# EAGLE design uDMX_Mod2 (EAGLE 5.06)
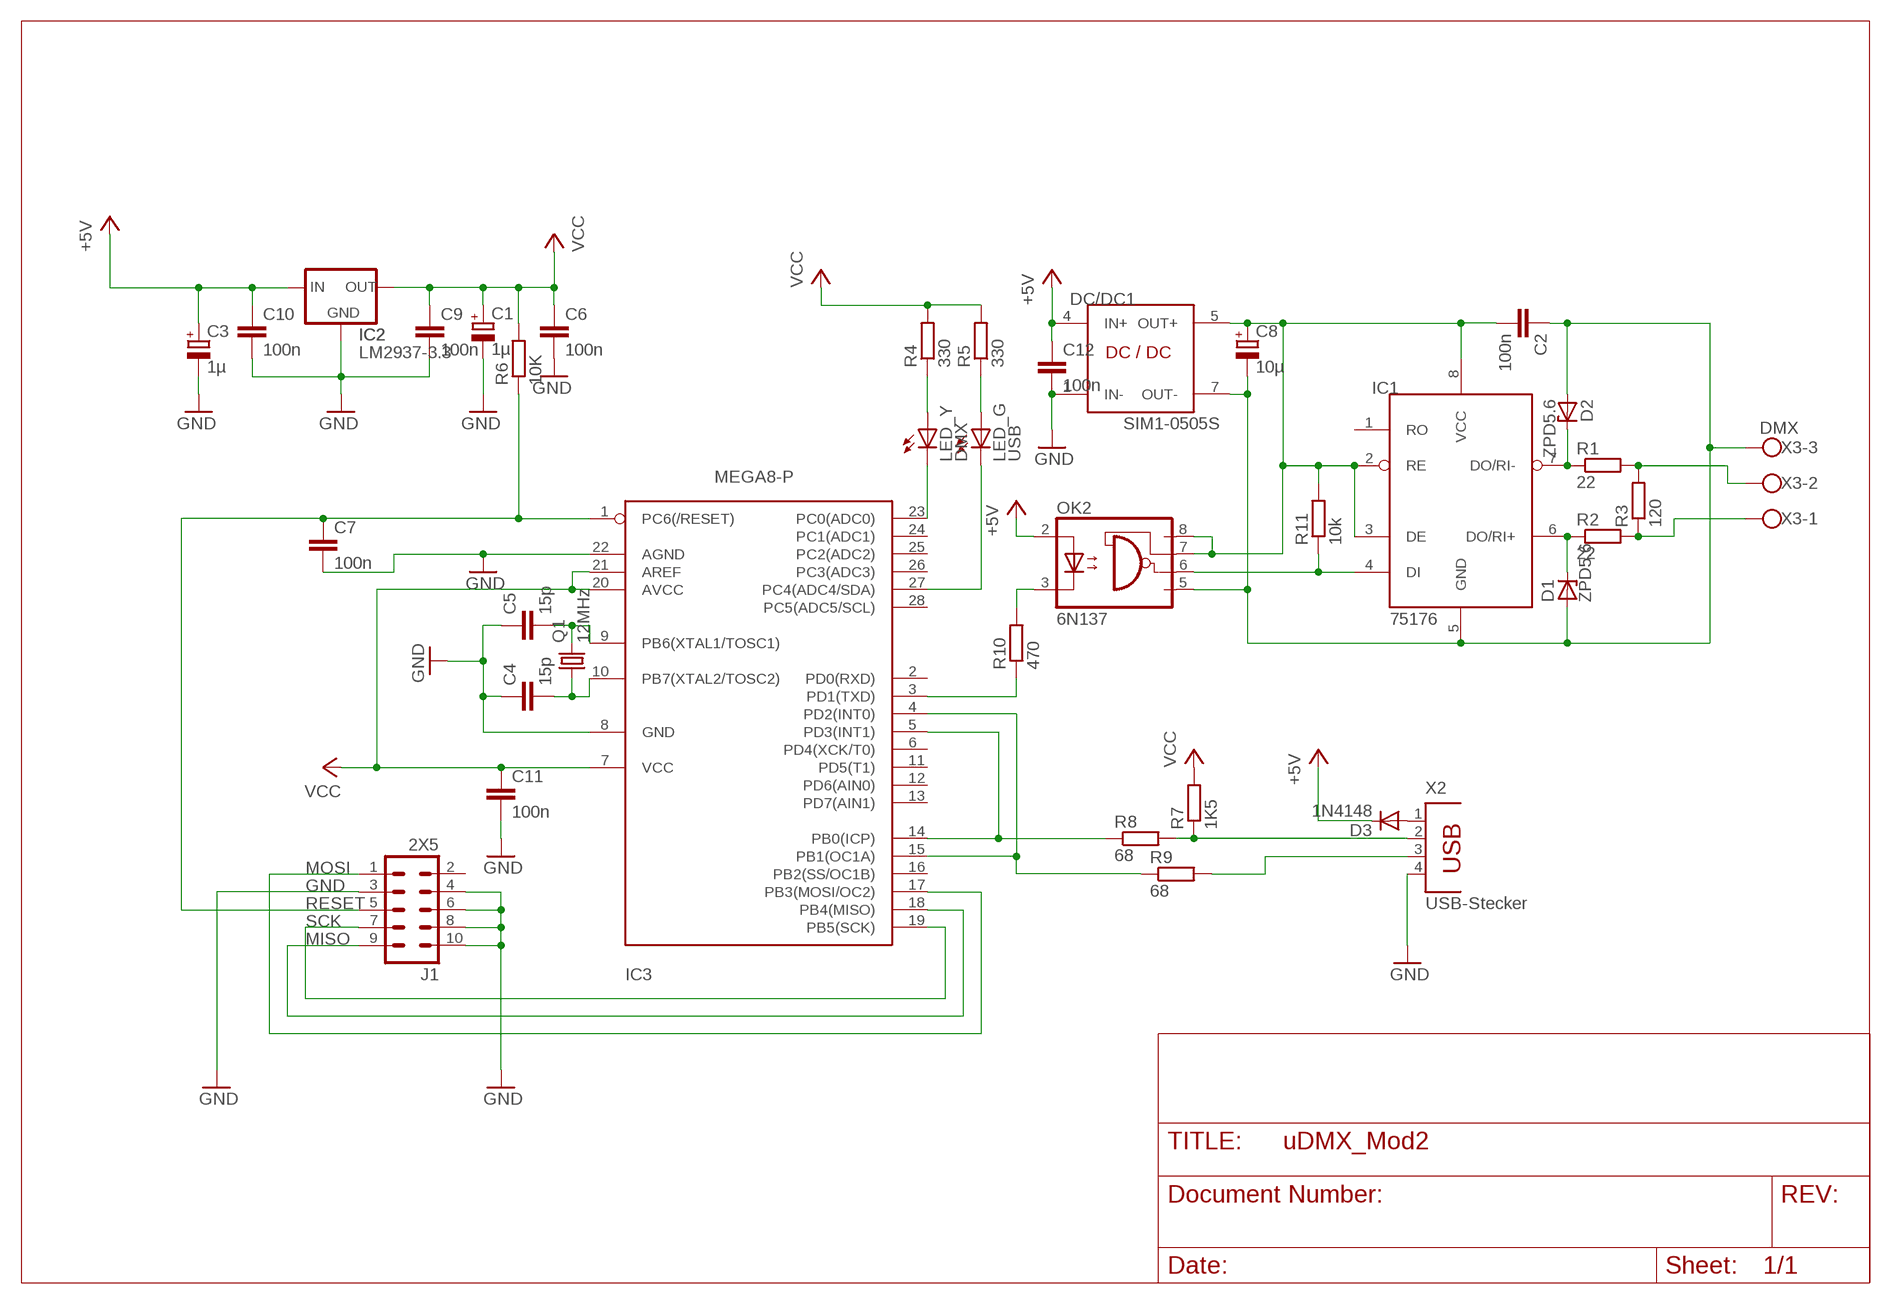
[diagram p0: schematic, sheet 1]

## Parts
C1  1µ  CPOL-EUE2.5-5  [E2,5-5]
C2  100n  C2.5/4  [C2.5-4]
C3  1µ  CPOL-EUE2.5-5  [E2,5-5]
C4  15p  C2.5/4  [C2.5-4]
C5  15p  C2.5/4  [C2.5-4]
C6  100n  C2.5/4  [C2.5-4]
C7  100n  C2.5/4  [C2.5-4]
C8  10µ  CPOL-EUE2.5-5  [E2,5-5]
C9  100n  C2.5/4  [C2.5-4]
C10  100n  C2.5/4  [C2.5-4]
C11  100n  C2.5/4  [C2.5-4]
C12  100n  C2.5/4  [C2.5-4]
D1  ZPD5.6  ZPD  [DO35Z10]
D2  ZPD5.6  ZPD  [DO35Z10]
D3  1N4148  [DO35-10]
DC/DC1  SIM1-0505S  [DIL08]
IC1  75176  [DIL08]
IC2  LM2937-3.3  LM2937  [TO220S]
IC3  MEGA8-P  [DIL28-3]
J1  2X5  [ML10]
LED_G  USB  LED3MM  [LED3MM]
LED_Y  DMX  LED3MM  [LED3MM]
OK2  6N137  [DIL08]
Q1  12MHz  CRYSTALHC49S  [HC49/S]
R1  22  R-EU_0207/2V  [0207/2V]
R2  22  R-EU_0207/2V  [0207/2V]
R3  120  R-EU_0207/5V  [0207/5V]
R4  330  R-EU_0207/2V  [0207/2V]
R5  330  R-EU_0207/2V  [0207/2V]
R6  10K  R-EU_0204/7  [0204/7]
R7  1K5  R-EU_0204/7  [0204/7]
R8  68  R-EU_0204/7  [0204/7]
R9  68  R-EU_0204/7  [0204/7]
R10  470  R-EU_0207/10  [0207/10]
R11  10k  R-EU_0204/7  [0204/7]
X2  USB-Stecker  PN61729  [PN61729]
X3  DMX  W237-3E  [W237-3E]

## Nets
+5V: C3.+ C10.1 C12.1 D3.C DC/DC1.4(IN+) IC2.1(IN) OK2.2(A)
D-: R7.1 R8.2 X2.2
DMX2: R1.2 R3.2 X3.2
GND: C1.- C3.- C4.1 C5.1 C6.2 C7.2 C9.2 C10.2 C11.2 C12.2 DC/DC1.1(IN-) IC2.2(GND) IC3.8(GND) IC3.22(AGND) J1.3 J1.4 J1.6 J1.8 J1.10 X2.4
MISO: IC3.18(PB4(MISO)) J1.9
MOSI: IC3.17(PB3(MOSI/OC2)) J1.1
N$1: IC3.5(PD3(INT1)) IC3.14(PB0(ICP)) R8.1
N$2: OK2.3(C) R10.2
N$3: D2.C IC1.7(DO/RI-) R1.1
N$4: D1.C IC1.6(DO/RI+) R2.2
N$5: IC3.3(PD1(TXD)) R10.1
N$6: IC3.4(PD2(INT0)) IC3.15(PB1(OC1A)) R9.1
N$7: LED_Y.A R4.1
N$8: LED_G.A R5.1
N$9: IC3.23(PC0(ADC0)) LED_Y.K(C)
N$10: R9.2 X2.3
N$11: IC3.27(PC4(ADC4/SDA)) LED_G.K(C)
N$13: R2.1 R3.1 X3.1
N$14: D3.A X2.1
N$16: C2.2 C8.+ DC/DC1.5(OUT+) IC1.2(RE) IC1.3(DE) IC1.8(VCC) OK2.7(VE) OK2.8(VCC) R11.2
N$17: C2.1 C8.- D1.A D2.A DC/DC1.7(OUT-) IC1.5(GND) OK2.5(GND) X3.3
N$20: IC1.4(DI) OK2.6(VO) R11.1
N$37: C4.2 IC3.10(PB7(XTAL2/TOSC2)) Q1.1
N$38: C5.2 IC3.9(PB6(XTAL1/TOSC1)) Q1.2
RESET: C7.1 IC3.1(PC6(/RESET)) J1.5 R6.1
SCK: IC3.19(PB5(SCK)) J1.7
VCC: C1.+ C6.1 C9.1 C11.1 IC2.3(OUT) IC3.7(VCC) IC3.20(AVCC) IC3.21(AREF) R4.2 R5.2 R6.2 R7.2
Unconnected: IC1.1(RO) IC3.2(PD0(RXD)) IC3.6(PD4(XCK/T0)) IC3.11(PD5(T1)) IC3.12(PD6(AIN0)) IC3.13(PD7(AIN1)) IC3.16(PB2(SS/OC1B)) IC3.24(PC1(ADC1)) IC3.25(PC2(ADC2)) IC3.26(PC3(ADC3)) IC3.28(PC5(ADC5/SCL)) J1.2

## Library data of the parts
C1 C3 C8 = rcl:CPOL-EU: POLARIZED CAPACITOR, European symbol
C2 C4-C7 C9-C12 = capacitor-wima:C: CAPACITOR
D1 D2 = diode:ZPD: Z DIODE
D3 = diode:1N4148: DIODE
DC/DC1 = Lutz:SIM1-0505S
IC1 = Lutz:75176
IC2 = Lutz:LM2937: VOLTAGE REGULATOR
IC3 = atmel:MEGA8-P: MICROCONTROLLER 8 Kbytes FLASH 1 kbytes SRAM 512 bytes EEPROM USART 4-channel 10 bit ADC 2-channel 8 bit ADC Source: avr.lbr
J1 = demo_WS2009:2X5
LED_G LED_Y = led:LED: LED
OK2 = optocoupler:6N137: MOTOROLA OPTO COUPLER
Q1 = crystal:CRYSTAL: CRYSTAL
R1-R11 = rcl:R-EU_: RESISTOR, European symbol
X2 = con-berg:PN61729: BERG USB connector
X3 = con-wago-508:W237-3E: WAGO SREW CLAMP

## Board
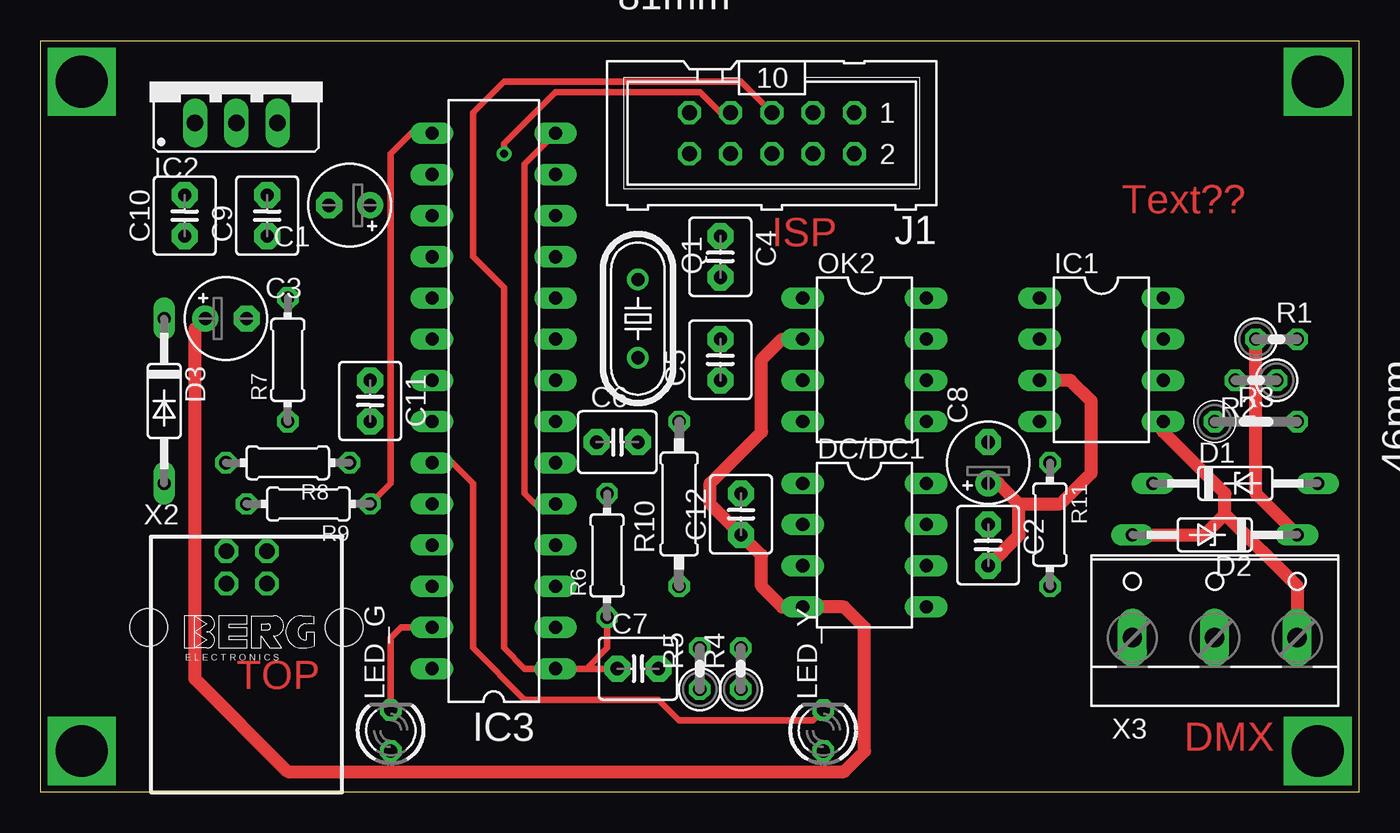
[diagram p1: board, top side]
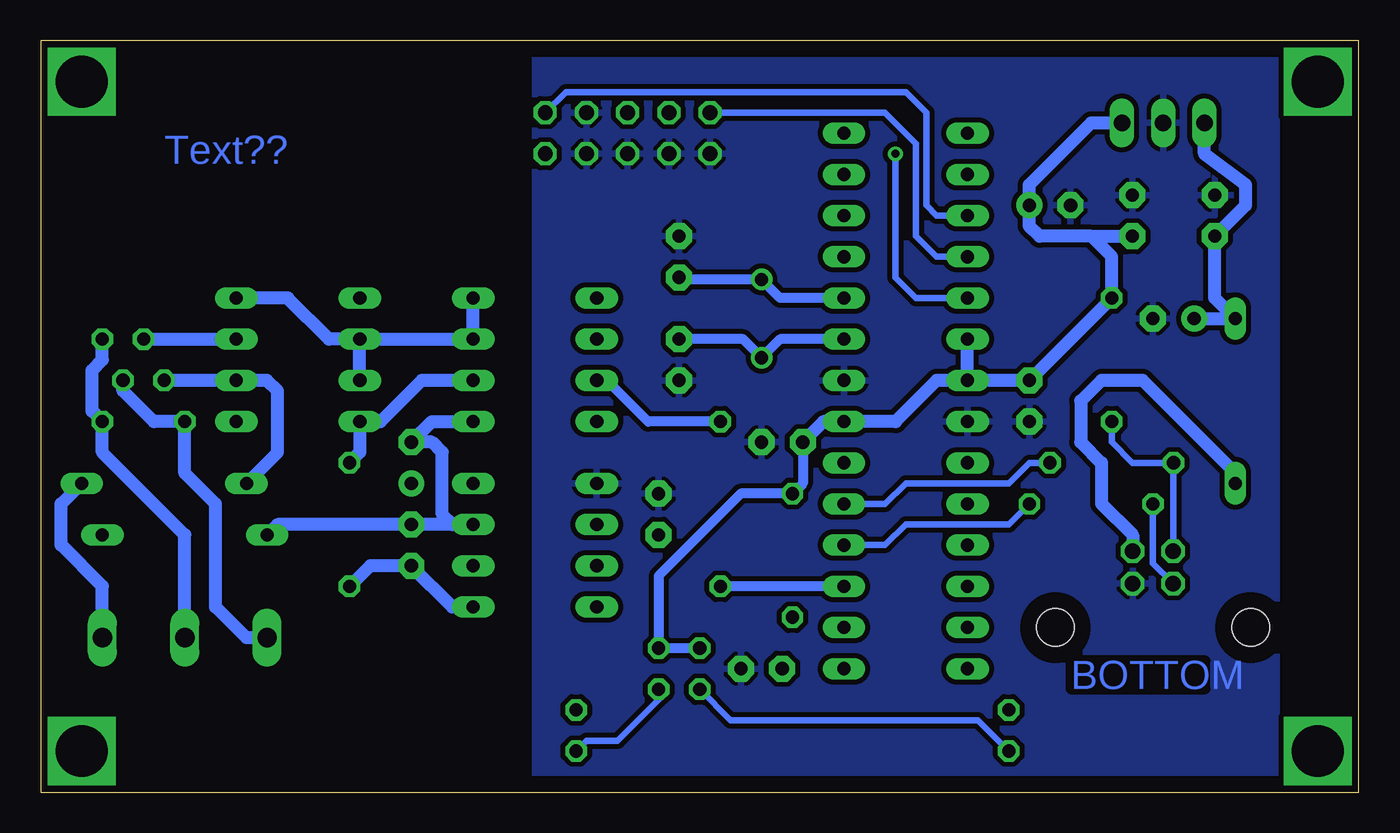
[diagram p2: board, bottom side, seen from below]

Size 81.28 x 46.35 mm. Coordinates in mm from the lower left corner, seen from the top.
Outline: 81.28,46.35 81.28,0 0,0 0,46.35 81.28,46.35
Copper layers (1*16): Top 0.035mm / dielectric 1.5mm / Bottom 0.035mm
Design rules "default": minimum track width 10mil, minimum drill 24mil, track to track 8mil, track to pad 8mil, pad to pad 8mil, via to via 8mil, smd to smd 8mil, copper to edge 40mil, drill to drill 8mil, minimum pad ring 10mil, minimum via ring 8mil, stop-mask expansion 4mil, vias tented up to drill 0mil, thermal gap 10mil

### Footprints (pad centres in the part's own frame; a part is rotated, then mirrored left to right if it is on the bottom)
E2,5-5 = drill 0.813 pad 1.6 round: + -1.27,0 | drill 0.813 pad 1.6 octagon: - 1.27,0
C2.5-4 = drill 0.813 pad 1.6 octagon: 1 -1.27,0; 2 1.27,0
DO35Z10 = drill 0.813 long: A 5.08,0; C -5.08,0
DO35-10 = drill 0.813 long: A 5.08,0; C -5.08,0
DIL08 = drill 0.813 long: 1 -3.81,-3.81; 2 -1.27,-3.81; 3 1.27,-3.81; 4 3.81,-3.81; 5 3.81,3.81; 6 1.27,3.81; 7 -1.27,3.81; 8 -3.81,3.81
TO220S = drill 1.016 long: 1 -2.54,-2.54; 2 0,-2.54; 3 2.54,-2.54
DIL28-3 = drill 0.813 long: 1 -16.51,-3.81; 2 -13.97,-3.81; 3 -11.43,-3.81; 4 -8.89,-3.81; 5 -6.35,-3.81; 6 -3.81,-3.81; 7 -1.27,-3.81; 8 1.27,-3.81; 9 3.81,-3.81; 10 6.35,-3.81; 11 8.89,-3.81; 12 11.43,-3.81; 13 13.97,-3.81; 14 16.51,-3.81; 15 16.51,3.81; 16 13.97,3.81; 17 11.43,3.81; 18 8.89,3.81; 19 6.35,3.81; 20 3.81,3.81; 21 1.27,3.81; 22 -1.27,3.81; 23 -3.81,3.81; 24 -6.35,3.81; 25 -8.89,3.81; 26 -11.43,3.81; 27 -13.97,3.81; 28 -16.51,3.81
ML10 = drill 0.914 octagon: 1 -5.08,-1.27; 2 -5.08,1.27; 3 -2.54,-1.27; 4 -2.54,1.27; 5 0,-1.27; 6 0,1.27; 7 2.54,-1.27; 8 2.54,1.27; 9 5.08,-1.27; 10 5.08,1.27
LED3MM = drill 0.813 octagon: A -1.27,0; K 1.27,0
HC49/S = drill 0.813 round: 1 -2.413,0; 2 2.413,0
0207/2V = drill 0.813 octagon: 1 -1.27,0; 2 1.27,0
0207/5V = drill 0.813 octagon: 1 -2.54,0; 2 2.54,0
0204/7 = drill 0.813 octagon: 1 -3.81,0; 2 3.81,0
0207/10 = drill 0.813 octagon: 1 -5.08,0; 2 5.08,0
PN61729 = drill 0.95 octagon: 1 1.25,4.71; 2 -1.25,4.71; 3 -1.25,2.71; 4 1.25,2.71 | hole 2.3: -6.02,0; 6.02,0
W237-3E = drill 1.194 long: 1 -5.08,-0.635; 2 0,-0.635; 3 5.08,-0.635

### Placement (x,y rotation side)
C1  19.05,36.2 180 top
C2  58.42,15.24 270 top
C3  11.43,29.21 0 top
C4  41.91,33.02 270 top
C5  41.91,26.67 90 top
C6  35.56,21.59 0 top
C7  36.83,7.62 0 top
C8  58.42,20.32 90 top
C9  13.97,35.56 90 top
C10  8.89,35.56 90 top
C11  20.32,24.13 270 top
C12  43.18,17.14 90 top
D1  73.66,19.05 0 top
D2  72.39,15.88 180 top
D3  7.62,24.13 270 top
DC/DC1  50.8,15.24 270 top
IC1  65.41,26.67 270 top
IC2  12.06,43.81 0 top
IC3  27.94,24.13 90 top
J1  45.09,40.64 180 top
LED_G  21.59,3.81 90 top
LED_Y  48.26,3.81 90 top
OK2  50.8,26.67 270 top
Q1  36.83,29.21 270 top
R1  76.2,27.94 0 top
R2  74.93,25.4 180 top
R3  74.93,22.86 0 top
R4  43.18,7.62 90 top
R5  40.64,7.62 90 top
R6  34.92,14.61 90 top
R7  15.24,26.67 90 top
R8  15.24,20.32 180 top
R9  16.51,17.78 180 top
R10  39.37,17.78 90 top
R11  62.23,16.51 270 top
X2  12.7,10.16 0 top
X3  72.39,10.16 0 top

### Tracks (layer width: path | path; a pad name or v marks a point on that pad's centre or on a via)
+5V
  Top 0.813: OK2.2 45.72,27.94 44.45,26.67 44.45,22.23 41.27,19.05 41.27,17.78 C12.1 44.45,14.61 44.45,12.7 45.72,11.43 DC/DC1.4 49.53,11.43 50.8,10.16 50.8,2.54 49.53,1.27 15.24,1.27 9.53,6.99 9.53,28.57 C3.+
  Bottom 0.813: C3.+ D3.C 8.89,30.48 C10.1 6.99,36.2 6.99,37.47 9.53,39.37 IC2.1
D-
  Bottom 0.406: X2.2 11.45,20.3 R8.2 13.97,20.32 15.24,21.59 R7.1
DMX2
  Bottom 0.813: X3.2 72.39,15.88 77.47,20.95 R3.2 78.11,23.5 78.11,26.04 77.47,26.67 R1.2
GND
  pour Bottom (isolate 0.305): 5.08,45.72 50.8,45.72 50.8,0.64 5.08,0.64
MISO
  Bottom 0.406: J1.9 29.21,41.91 27.3,40.01 27.3,34.29 26.04,33.02 IC3.18
MOSI
  Bottom 0.406: J1.1 48.9,43.18 27.94,43.18 26.67,41.91 26.67,36.2 26.04,35.56 IC3.17
N$1
  Top 0.406: IC3.14 29.84,38.73 29.84,18.41 30.48,17.78 IC3.5
  Bottom 0.406: R8.1 20.32,20.32 21.59,19.05 27.94,19.05 29.21,17.78 IC3.5
N$2
  Bottom 0.61: R10.2 43.81,22.86 46.35,25.4 OK2.3
N$3
  Top 0.813: R1.1 74.93,18.41 D2.C
  Bottom 0.813: R1.1 IC1.7
N$4
  Bottom 0.813: R2.2 IC1.6 67.31,25.4 66.67,24.77 66.67,20.95 D1.C
N$5
  Bottom 0.61: IC3.3 R10.1
N$6
  Top 0.406: IC3.15 22.86,40.64 21.59,39.37 21.59,19.05 R9.1
  Bottom 0.406: R9.1 21.59,16.51 27.94,16.51 29.21,15.24 IC3.4
N$7
  Bottom 0.406: R4.1 43.18,5.71 45.72,3.17 47.62,3.17 LED_Y.A
N$8
  Bottom 0.406: LED_G.A 23.5,4.45 38.73,4.45 R5.1
N$9
  Top 0.406: IC3.23 25.4,20.32 26.67,19.05 26.67,8.89 29.84,5.71 38.1,5.71 39.37,4.45 47.62,4.45 LED_Y.K
N$10
  Bottom 0.406: R9.2 12.7,14.12 X2.3
N$11
  Top 0.406: LED_G.K 21.59,9.53 22.23,10.16 IC3.27
N$12  (via drill 0.5)
  other vias: 28.57,39.37
N$13
  Bottom 0.813: X3.1 68.58,9.53 70.48,11.43 70.48,17.78 72.39,19.68 R3.1 74.3,22.86 76.2,24.77 R2.1
N$14
  Bottom 0.813: X2.1 13.95,15.86 15.88,17.78 15.88,20.32 17.14,21.59 17.14,24.13 15.88,25.4 13.34,25.4 7.62,19.68 D3.A
N$15  (via drill 3.2 pad 3.81)
  other vias: 78.74,43.81
N$16
  Top 0.813: C8.+ 59.05,19.05 60.33,17.78 | 60.33,17.78 60.33,15.88 C2.2 | 60.33,17.78 62.87,17.78 64.77,19.68 64.77,24.13 63.5,25.4 IC1.3
  Bottom 0.813: OK2.8 OK2.7 IC1.2 | IC1.2 63.5,27.94 66.04,30.48 IC1.8 | IC1.3 IC1.2 | DC/DC1.5 55.88,11.43 C2.2 60.96,13.97 R11.2
N$17
  Top 0.813: IC1.5 69.22,22.23 73.03,18.41 73.03,17.14 | 73.03,17.14 77.47,12.7 X3.3 | D2.A 71.75,15.88 73.03,17.14
  Bottom 0.813: X3.3 77.47,12.7 80.01,15.24 80.01,17.78 D1.A | OK2.5 57.15,22.86 C8.- 57.15,21.59 56.52,20.95 56.52,17.14 55.88,16.51 | DC/DC1.7 55.88,16.51 | 55.88,16.51 C2.1 66.67,16.51 D2.A
N$18  (via drill 3.2 pad 3.81)
  other vias: 78.74,2.54
N$19  (via drill 3.2 pad 3.81)
  other vias: 2.54,43.81
N$20
  Bottom 0.813: OK2.6 57.78,25.4 60.33,22.86 IC1.4 61.59,20.95 R11.1
N$21  (via drill 3.2 pad 3.81)
  other vias: 2.54,2.54
N$37
  Bottom 0.406: 41.78,31.62 C4.2
  Bottom 0.61: IC3.10 35.69,30.48 Q1.1 41.78,31.62
N$38
  Bottom 0.61: IC3.9 35.69,27.94 Q1.2 37.97,27.94 C5.2
RESET
  Top 0.406: J1.5 43.18,43.81 28.57,43.81 26.67,41.91 26.67,33.02 28.57,31.11 28.57,8.89 29.84,7.62 IC3.1 33.66,7.62 | 33.66,7.62 C7.1 | R6.1 34.92,8.89 33.66,7.62
SCK  (via drill 0.5)
  Top 0.406: J1.7 41.91,41.91 40.64,43.18 31.75,43.18 28.57,40.01 v28.57,39.37
  Bottom 0.406: v28.57,39.37 28.57,31.75 27.3,30.48 IC3.19
VCC
  Bottom 0.406: R4.2 R5.2
  Bottom 0.61: R5.2 R4.2 43.18,13.34 38.1,18.41 R6.2 34.29,19.05 C6.1
  Bottom 0.813: 16.51,34.29 C9.1 | 16.51,34.29 19.68,34.29 20.32,34.92 C1.+ 20.32,37.47 16.51,41.27 IC2.3 | IC3.21 C11.1 R7.2 15.24,33.02 16.51,34.29 | IC3.21 IC3.20 | IC3.21 26.04,25.4 28.57,22.86 IC3.7 33.02,22.86 C6.1

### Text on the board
Top: Text?? | ISP | TOP | DMX
Bottom: Text?? | BOTTOM
tPlace: 81mm | 46mm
